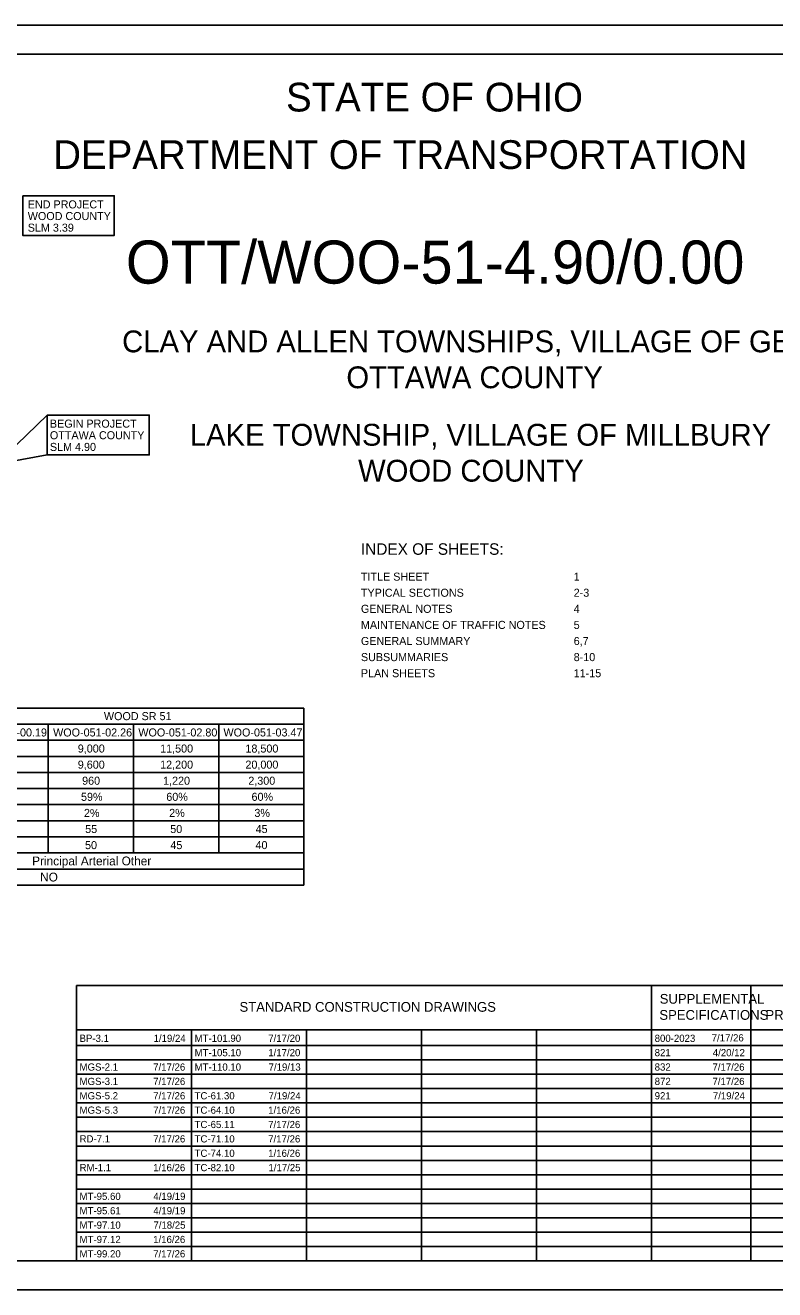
# Model space of a CAD drawing. Extents: x 0 to 34, y 0 to 22.
# Drawn here: x 9.26 to 22.29, y 0 to 22 of the extents above; entities that cross this region are included whole.
import ezdxf

# ---------------------------------------------------------------- set-up
doc = ezdxf.new("R2010")
doc.units = 0
for name, color, linetype in [('SH_Border', 7, 'Continuous'), ('SH_Cut_Line', 7, 'Continuous'), ('SH_Data', 7, 'Continuous'), ('SH_Text', 7, 'Continuous')]:
    doc.layers.add(name, color=color, linetype=linetype)

msp = doc.modelspace()

# ---------------------------------------------------------------- linework, layer by layer
at = {"layer": 'SH_Border'}
msp.add_lwpolyline([(1.5, 21.5), (33.5, 21.5), (33.5, 0.5), (1.5, 0.5)], close=True, dxfattribs=at)
at = {"layer": 'SH_Cut_Line'}
msp.add_lwpolyline([(0, 0), (34, 0), (34, 22), (0, 22)], close=True, dxfattribs=at)
at = {"layer": 'SH_Data'}
for p, q in [((5.212, 10.12), (14.106, 10.12)), ((14.106, 10.12), (14.106, 7.04)), ((2, 9.84), (14.106, 9.84)), ((9.659, 9.84), (9.659, 7.6)), ((11.141, 9.84), (11.141, 7.6)), ((12.624, 9.84), (12.624, 7.6)), ((2, 9.56), (14.106, 9.56)), ((2, 9.28), (14.106, 9.28)), ((2, 9), (14.106, 9)), ((2, 8.72), (14.106, 8.72)), ((2, 8.44), (14.106, 8.44)), ((2, 8.16), (14.106, 8.16)), ((2, 7.88), (14.106, 7.88)), ((2, 7.6), (14.106, 7.6)), ((2, 7.32), (14.106, 7.32)), ((2, 7.04), (14.106, 7.04)), ((10.15, 5.292), (23.6, 5.292)), ((10.15, 0.5), (10.15, 5.292)), ((20.15, 0.5), (20.15, 5.292)), ((21.875, 0.5), (21.875, 5.292)), ((10.15, 4.521), (23.6, 4.521)), ((12.15, 0.5), (12.15, 4.521)), ((14.15, 0.5), (14.15, 4.521)), ((16.15, 0.5), (16.15, 4.521)), ((18.15, 0.5), (18.15, 4.521)), ((10.15, 4.25), (23.6, 4.25)), ((10.15, 4), (23.6, 4)), ((10.15, 3.75), (23.6, 3.75)), ((10.15, 3.5), (23.6, 3.5)), ((10.15, 3.25), (23.6, 3.25)), ((10.15, 3), (23.6, 3)), ((10.15, 2.75), (23.6, 2.75)), ((10.15, 2.5), (23.6, 2.5)), ((10.15, 2.25), (23.6, 2.25)), ((10.15, 2), (23.6, 2)), ((10.15, 1.75), (23.6, 1.75)), ((10.15, 1.5), (23.6, 1.5)), ((10.15, 1.25), (23.6, 1.25)), ((10.15, 1), (23.6, 1)), ((10.15, 0.75), (23.6, 0.75))]:
    msp.add_line(p, q, dxfattribs=at)
at = {"layer": 'SH_Text'}
for points in [[(9.218, 19.035), (10.809, 19.035), (10.809, 18.343), (9.218, 18.343)], [(9.64, 15.218), (8.752, 14.361), (9.64, 14.526)], [(9.64, 15.218), (11.417, 15.218), (11.417, 14.526), (9.64, 14.526)]]:
    msp.add_lwpolyline(points, close=True, dxfattribs=at)

# ---------------------------------------------------------------- texts
for s, height, p in [('STATE OF OHIO', 0.5, (13.795, 20.5)), ('DEPARTMENT OF TRANSPORTATION', 0.5, (9.747, 19.5)), ('END PROJECT', 0.14, (9.304, 18.814)), ('WOOD COUNTY', 0.14, (9.304, 18.611)), ('SLM 3.39', 0.14, (9.304, 18.409)), ('OTT/WOO-51-4.90/0.00', 0.75, (11.009, 17.505)), ('CLAY AND ALLEN TOWNSHIPS, VILLAGE OF GENOA', 0.38, (10.945, 16.31)), ('OTTAWA COUNTY', 0.38, (14.844, 15.685)), ('BEGIN PROJECT', 0.14, (9.689, 14.999)), ('LAKE TOWNSHIP, VILLAGE OF MILLBURY', 0.38, (12.122, 14.685)), ('OTTAWA COUNTY', 0.14, (9.689, 14.797)), ('SLM 4.90', 0.14, (9.689, 14.594)), ('WOOD COUNTY', 0.38, (15.048, 14.06)), ('INDEX OF SHEETS:', 0.2, (15.097, 12.787)), ('TITLE SHEET', 0.14, (15.097, 12.337)), ('1', 0.14, (18.797, 12.337)), ('TYPICAL SECTIONS', 0.14, (15.097, 12.057)), ('2-3', 0.14, (18.797, 12.057)), ('GENERAL NOTES', 0.14, (15.097, 11.777)), ('4', 0.14, (18.797, 11.777)), ('MAINTENANCE OF TRAFFIC NOTES', 0.14, (15.097, 11.497)), ('5', 0.14, (18.797, 11.497)), ('GENERAL SUMMARY', 0.14, (15.097, 11.217)), ('6,7', 0.14, (18.797, 11.217)), ('SUBSUMMARIES', 0.14, (15.097, 10.937)), ('8-10', 0.14, (18.797, 10.937)), ('PLAN SHEETS', 0.14, (15.097, 10.657)), ('11-15', 0.14, (18.797, 10.657)), ('WOOD SR 51', 0.14, (10.628, 9.91)), ('WOO-051-00.19', 0.14, (8.264, 9.626)), ('WOO-051-02.26', 0.14, (9.745, 9.626)), ('WOO-051-02.80', 0.14, (11.227, 9.626)), ('WOO-051-03.47', 0.14, (12.707, 9.626)), ('9,000', 0.14, (10.174, 9.346)), ('11,500', 0.14, (11.606, 9.346)), ('18,500', 0.14, (13.089, 9.346)), ('9,600', 0.14, (10.174, 9.066)), ('12,200', 0.14, (11.606, 9.066)), ('20,000', 0.14, (13.089, 9.066)), ('960', 0.14, (10.249, 8.786)), ('1,220', 0.14, (11.657, 8.786)), ('2,300', 0.14, (13.139, 8.786)), ('59%', 0.14, (10.23, 8.506)), ('60%', 0.14, (11.713, 8.506)), ('60%', 0.14, (13.195, 8.506)), ('2%', 0.14, (10.281, 8.226)), ('2%', 0.14, (11.763, 8.226)), ('3%', 0.14, (13.245, 8.226)), ('55', 0.14, (10.302, 7.946)), ('50', 0.14, (11.782, 7.946)), ('45', 0.14, (13.266, 7.946)), ('50', 0.14, (10.3, 7.666)), ('45', 0.14, (11.784, 7.666)), ('40', 0.14, (13.264, 7.666)), ('Principal Arterial Other', 0.154, (9.38, 7.383)), ('NO', 0.154, (9.519, 7.103)), ('SUPPLEMENTAL', 0.17, (20.293, 4.976)), ('STANDARD CONSTRUCTION DRAWINGS', 0.17, (12.986, 4.836)), ('SPECIFICATIONS', 0.17, (20.287, 4.696)), ('PROVISIONS', 0.17, (22.132, 4.696)), ('BP-3.1', 0.125, (10.205, 4.312)), ('1/19/24', 0.125, (11.492, 4.312)), ('MT-101.90', 0.125, (12.205, 4.312)), ('7/17/20', 0.125, (13.486, 4.312)), ('800-2023', 0.125, (20.205, 4.312)), ('7/17/26', 0.125, (21.196, 4.32)), ('MT-105.10', 0.125, (12.205, 4.062)), ('1/17/20', 0.125, (13.486, 4.062)), ('821', 0.125, (20.205, 4.062)), ('4/20/12', 0.125, (21.216, 4.062)), ('MGS-2.1', 0.125, (10.205, 3.812)), ('7/17/26', 0.125, (11.485, 3.812)), ('MT-110.10', 0.125, (12.205, 3.812)), ('7/19/13', 0.125, (13.492, 3.812)), ('832', 0.125, (20.205, 3.812)), ('7/17/26', 0.125, (21.21, 3.812)), ('MGS-3.1', 0.125, (10.205, 3.562)), ('7/17/26', 0.125, (11.485, 3.562)), ('872', 0.125, (20.205, 3.562)), ('7/17/26', 0.125, (21.21, 3.562)), ('MGS-5.2', 0.125, (10.205, 3.312)), ('7/17/26', 0.125, (11.485, 3.312)), ('TC-61.30', 0.125, (12.205, 3.312)), ('7/19/24', 0.125, (13.492, 3.312)), ('921', 0.125, (20.205, 3.312)), ('7/19/24', 0.125, (21.217, 3.312)), ('MGS-5.3', 0.125, (10.205, 3.062)), ('7/17/26', 0.125, (11.485, 3.062)), ('TC-64.10', 0.125, (12.205, 3.062)), ('1/16/26', 0.125, (13.485, 3.062)), ('TC-65.11', 0.125, (12.205, 2.812)), ('7/17/26', 0.125, (13.485, 2.812)), ('RD-7.1', 0.125, (10.205, 2.562)), ('7/17/26', 0.125, (11.485, 2.562)), ('TC-71.10', 0.125, (12.205, 2.562)), ('7/17/26', 0.125, (13.485, 2.562)), ('TC-74.10', 0.125, (12.205, 2.312)), ('1/16/26', 0.125, (13.485, 2.312)), ('RM-1.1', 0.125, (10.205, 2.062)), ('1/16/26', 0.125, (11.485, 2.062)), ('TC-82.10', 0.125, (12.205, 2.062)), ('1/17/25', 0.125, (13.489, 2.062)), ('MT-95.60', 0.125, (10.205, 1.562)), ('4/19/19', 0.125, (11.488, 1.562)), ('MT-95.61', 0.125, (10.205, 1.312)), ('4/19/19', 0.125, (11.488, 1.312)), ('MT-97.10', 0.125, (10.205, 1.062)), ('7/18/25', 0.125, (11.489, 1.062)), ('MT-97.12', 0.125, (10.205, 0.812)), ('1/16/26', 0.125, (11.485, 0.812)), ('MT-99.20', 0.125, (10.205, 0.562)), ('7/17/26', 0.125, (11.485, 0.562))]:
    msp.add_text(s, height=height, dxfattribs=at).set_placement(p)

doc.saveas('drawing.dxf')
